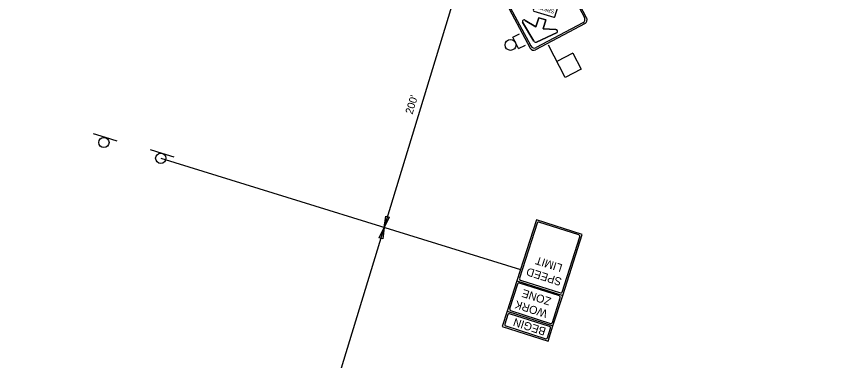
# Model space of a CAD drawing. Extents: x 2135767 to 2151731, y 141839 to 175894.
# Drawn here: x 2141258 to 2141896, y 170304 to 170573 of the extents above; entities that cross this region are included whole.
import ezdxf

# ---------------------------------------------------------------- set-up
doc = ezdxf.new("R2010")
doc.units = 0
for name, color, linetype in [('5', 7, 'Continuous'), ('Default', 7, 'Continuous'), ('PR_Dimensions', 7, 'Continuous'), ('PR_Dimensions_Phase', 7, 'Continuous'), ('PR_Phasing_Detour_1', 7, 'Continuous'), ('PR_Traffic_Control_Devices_Temp', 7, 'Continuous'), ('PR_Traffic_Sign_Temp', 7, 'Continuous'), ('PR_Txt', 7, 'Continuous')]:
    doc.layers.add(name, color=color, linetype=linetype)

# ---------------------------------------------------------------- blocks, each defined once
blk = doc.blocks.new('Arrowhd')
at = {"layer": 'Default'}
blk.add_lwpolyline([(0.318, -0.053), (0.318, 0.053), (0, 0)], close=True, dxfattribs=at)
blk = doc.blocks.new('R2-1E')
at = {"layer": 'Default'}
for p, q in [((7.62, 10.16), (0, 10.16)), ((0, 10.16), (0, 0)), ((0.25, 9.68), (0.25, 0.48)), ((7.14, 9.91), (0.48, 9.91)), ((7.37, 0.48), (7.37, 9.68)), ((7.62, 0), (7.62, 10.16)), ((0, 0), (7.62, 0)), ((0.48, 0.25), (7.14, 0.25))]:
    blk.add_line(p, q, dxfattribs=at)
for centre, start, end in [((0.48, 9.68), 90, 180), ((7.14, 9.68), 0, 90), ((0.48, 0.48), 180, 270), ((7.14, 0.48), 270, 0)]:
    blk.add_arc(centre, 0.222, start, end, dxfattribs=at)
for s, p in [('SPEED', (0.85, 7.62)), ('LIMIT', (1.44, 5.5))]:
    blk.add_text(s, height=1.27, dxfattribs=at).set_placement(p)
blk = doc.blocks.new('CS-14E')
at = {"layer": 'Default'}
for p, q in [((7.62, 2.54), (0, 2.54)), ((0, 2.54), (0, -2.54)), ((0.25, 2.06), (0.25, -2.06)), ((7.14, 2.29), (0.48, 2.29)), ((7.37, -2.06), (7.37, 2.06)), ((7.62, -2.54), (7.62, 2.54)), ((7.62, -2.54), (0, -2.54)), ((0.48, -2.29), (7.14, -2.29))]:
    blk.add_line(p, q, dxfattribs=at)
for centre, start, end in [((0.48, 2.06), 90, 180), ((7.14, 2.06), 0, 90), ((0.48, -2.06), 180, 270), ((7.14, -2.06), 270, 0)]:
    blk.add_arc(centre, 0.222, start, end, dxfattribs=at)
for s, p in [('WORK', (1.48, 0.44)), ('ZONE', (1.53, -1.6))]:
    blk.add_text(s, height=1.27, dxfattribs=at).set_placement(p)
blk = doc.blocks.new('CS-13E')
at = {"layer": 'Default'}
for p, q in [((0, 2.54), (0, 0)), ((7.62, 2.54), (0, 2.54)), ((0.25, 2.06), (0.25, 0.48)), ((7.14, 2.29), (0.48, 2.29)), ((7.37, 0.48), (7.37, 2.06)), ((7.62, 0), (7.62, 2.54)), ((7.62, 0), (0, 0)), ((0.48, 0.25), (7.14, 0.25))]:
    blk.add_line(p, q, dxfattribs=at)
for centre, start, end in [((0.48, 2.06), 90, 180), ((7.14, 2.06), 0, 90), ((0.48, 0.48), 180, 270), ((7.14, 0.48), 270, 0)]:
    blk.add_arc(centre, 0.222, start, end, dxfattribs=at)
blk.add_text('BEGIN', height=1.27, dxfattribs=at).set_placement((0.85, 0.64))
blk = doc.blocks.new('W3-5')
at = {"layer": '5'}
for p, q in [((0.81, 7.63), (6.73, 13.56)), ((13.56, 7.63), (7.63, 13.56)), ((6.73, 0.81), (0.81, 6.74)), ((7.63, 0.81), (13.56, 6.74))]:
    blk.add_line(p, q, dxfattribs=at)
for centre, start, end in [((7.18, 13.11), 45, 135), ((1.26, 7.18), 135, 225), ((13.11, 7.18), 315, 45), ((7.18, 1.26), 225, 315)]:
    blk.add_arc(centre, 0.635, start, end, dxfattribs=at)
at = {"layer": 'Default'}
for p, q in [((0.45, 7.63), (6.73, 13.92)), ((13.92, 7.63), (7.63, 13.92)), ((6.95, 12.72), (4.28, 10.3)), ((9.98, 10.32), (7.37, 12.69)), ((5.35, 8.02), (5.35, 3.42)), ((8.8, 8.13), (5.46, 8.13)), ((8.91, 3.42), (8.91, 8.02)), ((6.73, 0.45), (0.45, 6.74)), ((7.63, 0.45), (13.92, 6.74)), ((5.46, 3.3), (8.8, 3.3))]:
    blk.add_line(p, q, dxfattribs=at)
for points in [[(4.28, 10.3), (6.95, 12.72)], [(7.37, 12.69), (9.98, 10.32)], [(4.58, 9.92), (6.55, 10.41), (6.55, 8.91), (7.74, 8.91), (7.74, 10.45), (9.68, 9.96)], [(9.68, 9.96), (7.74, 10.45), (7.74, 8.91), (6.55, 8.91), (6.55, 10.41), (4.58, 9.92)]]:
    blk.add_lwpolyline(points, dxfattribs=at)
for centre, radius, start, end in [((7.18, 13.47), 0.635, 45, 135), ((7.14, 12.51), 0.285, 37.9142, 132.1493), ((7.14, 12.51), 0.285, 37.9142, 132.1493), ((4.52, 10.19), 0.269, 154.0903, 283.9085), ((4.52, 10.19), 0.269, 154.0903, 283.9085), ((9.83, 10.15), 0.237, 231.3417, 47.9123), ((9.83, 10.15), 0.237, 231.3417, 47.9123), ((5.46, 8.02), 0.111, 90, 180), ((8.8, 8.02), 0.111, 0, 90), ((0.9, 7.18), 0.635, 135, 225), ((13.47, 7.18), 0.635, 315, 45), ((5.46, 3.42), 0.111, 180, 270), ((8.8, 3.42), 0.111, 270, 0), ((7.18, 0.9), 0.635, 225, 315)]:
    blk.add_arc(centre, radius, start, end, dxfattribs=at)
for s, p in [('SPEED', (5.65, 6.99)), ('LIMIT', (5.95, 5.93))]:
    blk.add_text(s, height=0.635, dxfattribs=at).set_placement(p)
blk = doc.blocks.new('FLSHFLAG')
at = {"layer": 'PR_Txt'}
for p, q in [((-1.2, 14.13), (0.84, 16.15)), ((0.84, 16.15), (4.9, 12.08)), ((0.82, 12.08), (-1.2, 14.13)), ((0.82, 12.08), (2.86, 14.11)), ((9.26, 14), (8.4, 13.15)), ((9.26, 14), (10.68, 12.58)), ((10.68, 12.58), (9.83, 11.72))]:
    blk.add_line(p, q, dxfattribs=at)
blk.add_circle((10.65, 13.84), 0.873, dxfattribs=at)

msp = doc.modelspace()

# ---------------------------------------------------------------- linework, layer by layer
at = {"layer": 'PR_Dimensions'}
msp.add_line((2141457.71, 170121.37), (2141625.38, 170670.88), dxfattribs=at)
at = {"layer": 'PR_Dimensions_Phase'}
msp.add_line((2141370.65, 170461.91), (2141651.46, 170375.04), dxfattribs=at)
at = {"layer": 'PR_Phasing_Detour_1'}
msp.add_circle((2140069.54, 171591.41), 4302.23, dxfattribs=at)
at = {"layer": 'PR_Traffic_Sign_Temp'}
for p, q in [((2141327.49, 170478.05), (2141318.28, 170480.93)), ((2141336.71, 170475.17), (2141327.49, 170478.05)), ((2141371.84, 170465.73), (2141362.63, 170468.6)), ((2141381.05, 170462.85), (2141371.84, 170465.73))]:
    msp.add_line(p, q, dxfattribs=at)
for centre in [(2141326.3, 170474.23), (2141370.65, 170461.91)]:
    msp.add_circle(centre, 4, dxfattribs=at)

# ---------------------------------------------------------------- block references
at = {"layer": 'PR_Dimensions'}
for p, xscale, yscale, rotation in [((2141545.07, 170407.92), 27.559000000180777, -27.559000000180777, 72.9660298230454), ((2141545.14, 170407.93), 27.55900000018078, -27.55900000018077, -107.03397017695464)]:
    msp.add_blockref('Arrowhd', p, dxfattribs=dict(at, xscale=xscale, yscale=yscale, rotation=rotation))
at = {"layer": 'PR_Traffic_Control_Devices_Temp'}
for name, p, xscale, yscale, rotation in [('W3-5', (2141714.87, 170602.45), 4.921250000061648, 4.921250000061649, 163.0193420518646), ('FLSHFLAG', (2141714.17, 170599.48), 4.921250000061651, 4.921250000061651, 162.41849638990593), ('R2-1E', (2141699.65, 170402.57), 4.92125000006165, 4.921250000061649, 162.23599518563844), ('CS-14E', (2141680.59, 170343.05), 4.921249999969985, 4.9212499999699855, 162.23599518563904), ('CS-13E', (2141676.77, 170331.14), 4.921249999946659, 4.921249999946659, 162.23599517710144)]:
    msp.add_blockref(name, p, dxfattribs=dict(at, xscale=xscale, yscale=yscale, rotation=rotation))

# ---------------------------------------------------------------- texts
at = {"layer": 'Default'}
msp.add_text("200'", height=6, rotation=72.96603, dxfattribs=at).set_placement((2141567.08, 170495.81))

doc.saveas('drawing.dxf')
